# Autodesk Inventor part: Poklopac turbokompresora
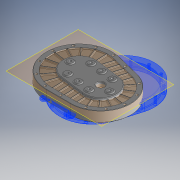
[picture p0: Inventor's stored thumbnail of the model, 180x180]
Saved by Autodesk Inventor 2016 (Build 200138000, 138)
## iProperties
Created: 2015-08
Part Number: Poklopac turbokompresora
Material: Generic
Document SubType Name: Modeling
Designer: stank
Density: 1 g/cm^3
Appearance: Default
Mass: 768.243 g
Surface Area: 1861.56 cm^2
Volume: 768.243 cm^3
Author: stank
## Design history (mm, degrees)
workplane "Work Plane3"
sketch "Sketch3"
  geometry: L1 (25.713, -105.228)-(-56.137, -104.923); L2 (26.085, -5.229)-(-52.114, 11.649); L3 (26.085, -5.229)-(-55.727, 5.076); L4 (25.769, -90.228)-(-56.081, -89.923); L5 (-32.512, 97.196)-(46.857, 77.194); L6 (50.522, 91.74)-(-28.846, 111.741); C1 r 9 at (26.085, -5.229) reference; C2 r 4.5 at (43.468, -93.366) reference; C3 r 4.5 at (-58.597, -126.199) reference; C4 r 4.5 at (-148.255, -75.856) reference; C5 r 4.5 at (-134.233, 101.873) reference; C6 r 4.5 at (-46.759, 125.523) reference; C7 r 4.5 at (25.538, 82.325) reference; A1 r 100 centre (26.085, -5.229) between (25.713, -105.228) and (50.522, 91.74); A2 r 110 centre (-55.727, 5.076) between (-28.846, 111.741) and (-56.137, -104.923); A3 r 85 centre (26.085, -5.229) between (25.769, -90.228) and (46.857, 77.194); A4 r 95 centre (-55.727, 5.076) between (-32.512, 97.196) and (-56.081, -89.923); 1 further point
  constraints: 12 end point, 8 point on circle, 6 tangent, 4 centre point, 2 parallel, 2 other
  dimensions: "d7" = 110 radius of A2; "d8" = 100 radius of A1; "d18" = 5 deg angle of L2 L3; "d26" = 15 distance between parallel lines of L1 L4; "d148" = 15 radial gap between concentric circles of A1 A3
extrude "Extrusion1" new body sketch "Sketch3" distance "d13" = 25; taper "d14" = 0 deg
sketch "Sketch7"
  geometry: L1 (50.522, 91.74)-(-28.846, 111.741) reference; L2 (-56.137, -104.923)-(25.713, -105.228) reference; C1 r 4 at (-41.402, 31.566) reference; C2 r 4 at (-38.197, -5.064) reference; C3 r 4 at (-13.762, -8.715) reference; C4 r 4 at (-4.556, 20.483) reference; C5 r 4 at (22.599, 34.619) reference; C6 r 4 at (51.797, 25.413) reference; C7 r 4 at (65.933, -1.742) reference; C8 r 4 at (56.727, -30.94) reference; C9 r 4 at (31.273, -44.891) reference; C10 r 4 at (0.374, -35.87) reference; A1 r 110 centre (-55.727, 5.076) between (-28.846, 111.741) and (-56.137, -104.923) reference; A2 r 100 centre (26.085, -5.229) between (25.713, -105.228) and (50.522, 91.74) reference; 1 further point
extrude "Extrusion3" join sketch "Sketch7" distance "d42" = 10; taper "d43" = 0 deg
sketch "Sketch8"
  geometry: L1 (25.769, -90.228)-(-56.081, -89.923) reference; L2 (-32.512, 97.196)-(46.857, 77.194) reference; C1 r 4 at (65.933, -1.742) reference; C2 r 4 at (56.727, -30.94) reference; C3 r 4 at (31.273, -44.891) reference; C4 r 4 at (0.374, -35.87) reference; C5 r 4 at (-13.762, -8.715) reference; C6 r 4 at (-38.197, -5.064) reference; C7 r 4 at (-4.556, 20.483) reference; C8 r 4 at (22.599, 34.619) reference; C9 r 4 at (51.797, 25.413) reference; C10 r 4 at (-41.402, 31.566) reference; C11 r 10 at (65.933, -1.742); C12 r 10 at (56.727, -30.94); C13 r 4 at (31.273, -44.891) reference; C14 r 10 at (31.273, -44.891); C15 r 10 at (0.374, -35.87); C16 r 4 at (-13.762, -8.715) reference; C17 r 10 at (-13.762, -8.715); C18 r 10 at (-38.197, -5.064); C19 r 10 at (-41.402, 31.566); C20 r 10 at (-4.556, 20.483); C21 r 4 at (22.599, 34.619) reference; C22 r 10 at (22.599, 34.619); C23 r 10 at (51.797, 25.413); A1 r 85 centre (26.085, -5.229) between (25.769, -90.228) and (46.857, 77.194) reference; A2 r 95 centre (-55.727, 5.076) between (-32.512, 97.196) and (-56.081, -89.923) reference; 1 further point
  constraints: 10 centre point, 10 coincident
  dimensions: "d44" = 20 diameter of C11; "d45" = 20 diameter of C12; "d46" = 20 diameter of C14; "d47" = 20 diameter of C15; "d48" = 20 diameter of C17; "d49" = 20 diameter of C20; "d50" = 20 diameter of C22; "d51" = 20 diameter of C23; "d52" = 20 diameter of C18; "d54" = 20 diameter of C19
extrude "Extrusion5" cut sketch "Sketch8" distance "d58" = 5; taper "d59" = 0 deg
sketch "Sketch10"
  geometry: C1 r 10 at (26.085, -5.229) reference; C2 r 11 at (26.085, -5.229); C3 r 16 at (26.085, -5.229); 1 further point
  constraints: 2 centre point, 2 coincident
  dimensions: "d60" = 1 radial gap between concentric circles of C1 C2; "d61" = 5 radial gap between concentric circles of C2 C3
extrude "Extrusion6" join sketch "Sketch10" distance "d62" = 3; taper "d63" = 0 deg
sketch "Sketch11"
  geometry: C1 r 11 at (0, 0) reference; 1 further point
extrude "Extrusion7" cut sketch "Sketch11" stored distance "d64" = 17; taper "d65" = 0 deg
chamfer "Chamfer3" distance "d71" = 1; stored, may be unused: second distance "d72" = 2, angle "d73" = 45 deg
workplane "Work Plane4"
sketch "Sketch12"
  geometry: L1 (26.085, -5.229)-(142.594, 145.734); L2 (26.085, -5.229)-(154.434, 22.85); L3 (26.085, -5.229)-(167.155, -24.202); L4 (26.085, -5.229)-(157.504, 77.979); L5 (101.371, 11.241)-(82.975, 7.217); L6 (89.461, -13.752)-(105.105, -15.856); L7 (75.965, 59.402)-(67.391, 48.291); L8 (92.041, 36.531)-(78.659, 28.059); L9 (-29.09, 110.772)-(50.278, 90.77) reference; L10 (25.717, -104.228)-(-56.133, -103.923) reference; L11 (-25.39, 100.364)-(51.872, 75.766) reference; L12 (30.981, -90.088)-(-49.967, -94.758) reference; L13 (-55.727, 5.076)-(-59.81, 104.993); L14 (-55.727, 5.076)-(-93.737, 97.571); L15 (-55.727, 5.076)-(-123.08, 78.992); L16 (-55.727, 5.076)-(-144.299, 51.499); L17 (-55.727, 5.076)-(-154.834, 18.406); L18 (-55.727, 5.076)-(-153.416, -16.295); L19 (-55.727, 5.076)-(26.085, -5.229); L20 (26.085, -5.229)-(51.872, 75.766); L21 (26.085, -5.229)-(51.872, 75.766); L22 (4.813, -2.549)-(31.782, 82.161); L23 (4.813, -2.549)-(8.443, -91.388); L24 (12.725, 88.229)-(-15.367, -0.007); L25 (-15.367, -0.007)-(-11.586, -92.543); L26 (-31.615, -93.699)-(-35.547, 2.534); L27 (-55.727, 5.076)-(-25.39, 100.364); L28 (-6.333, 94.296)-(-35.547, 2.534); L29 (49.768, 69.156)-(45.412, 55.475); L30 (49.768, 69.156)-(44.535, 52.72); L31 (29.678, 75.552)-(25.322, 61.871); L32 (9.933, 79.461)-(6.511, 68.711); L33 (-8.264, 88.229)-(-12.767, 74.086); L34 (-28.182, 91.595)-(-33.756, 74.086); L35 (-59.441, 95.979)-(-58.836, 81.156); L36 (-90.32, 89.255)-(-83.292, 72.154); L37 (-119.318, 74.864)-(-107.974, 62.414); L38 (-121.726, 39.668)-(-133.857, 46.026); L39 (-122.61, 14.072)-(-138.942, 16.268); L40 (-117.386, -8.413)-(-135.718, -12.423); L41 (-52.925, -63.49)-(-52.216, -80.841); L42 (-32.666, -67.96)-(-32.069, -82.577); L43 (-12.596, -67.814)-(-11.825, -86.696); L44 (7.37, -65.125)-(8.077, -82.428); L45 (26.085, -5.229)-(101.371, -44.688); L46 (26.085, -5.229)-(83.335, -68.057); L47 (26.085, -5.229)-(58.394, -83.849); L48 (26.085, -5.229)-(29.556, -90.158); L49 (-55.727, 5.076)-(-140.216, -48.418); L50 (-55.727, 5.076)-(-116.824, -74.089); L51 (-55.727, 5.076)-(-86.064, -90.211); L52 (-55.727, 5.076)-(-51.644, -94.84); L53 (83.335, -35.235)-(95.897, -41.818); L54 (65.44, -48.418)-(77.011, -61.116); L55 (49.052, -61.116)-(54.383, -74.089); L56 (28.634, -67.603)-(29.2, -81.44); L57 (-78.06, -65.073)-(-82.518, -79.075); L58 (-97.971, -49.661)-(-106.812, -61.116); L59 (-110.873, -29.84)-(-129.792, -41.818); C1 r 11 at (26.085, -5.229); C2 r 11 at (26.085, -5.229) reference; A1 r 100 centre (26.085, -5.229) between (25.713, -105.228) and (50.522, 91.74) reference; A2 r 110 centre (-55.727, 5.076) between (-28.846, 111.741) and (-56.137, -104.923) reference; A3 r 99 centre (26.085, -5.229) between (25.717, -104.228) and (50.278, 90.77) reference; A4 r 109 centre (-55.727, 5.076) between (-29.09, 110.772) and (-56.133, -103.923) reference; A5 r 85 centre (26.085, -5.229) between (30.981, -90.088) and (51.872, 75.766) reference; A6 r 100 centre (-55.727, 5.076) between (-25.39, 100.364) and (-49.967, -94.758) reference; A7 r 85 centre (26.085, -5.229) between (25.769, -90.228) and (46.857, 77.194) reference; A8 r 85 centre (26.085, -5.229) between (25.769, -90.228) and (46.857, 77.194) reference; 3 further points; 3 other entities
  constraints: 110 end point, 54 point on line, 14 point on circle, 6 parallel, 1 centre point, 1 coincident, 1 collinear, 1 perpendicular, 25 other
  dimensions: "d81" = 20 deg angle of L1 L4; "d82" = 20 deg angle of L2 L4; "d83" = 20 deg angle of L2 L3; "d194" = 20 deg angle of L13 L27; "d195" = 20 deg angle of L14 L13; "d196" = 20 deg angle of L14 L15; "d199" = 20 deg angle of L17 L16; "d200" = 20 deg angle of L17 L18; "d206" = 20 deg angle of L20 L1; "d207" = 20 deg angle of L15 L16; "d208" = 20 deg angle of L45 L3; "d209" = 20 deg angle of L46 L45; "d211" = 20 deg angle of L47 L46; "d212" = 20 deg angle of L48 L47; "d213" = 20 deg angle of L49 L18; "d214" = 20 deg angle of L50 L49; "d215" = 20 deg angle of L51 L50; "d216" = 20 deg angle of L51 L52; "d217" = 20 distance between parallel lines of L27 L28; "d218" = 20 distance between parallel lines of L24 L28; "d219" = 20 distance between parallel lines of L24 L22
  node "Projected Loop13"
sketch "Sketch13"
  geometry: L1 (26.085, -5.229)-(-31.513, 2.026); L2 (26.085, -5.229)-(-174.711, 20.063) reference; L3 (-55.727, 5.076)-(26.085, -5.229); L4 (-62.6, -49.493)-(19.212, -59.798); L5 (32.959, 49.34)-(-48.853, 59.645); A1 r 100 centre (-55.727, 5.076) between (-25.39, 100.364) and (-49.967, -94.758) reference; A2 r 55 centre (-55.727, 5.076) between (-48.853, 59.645) and (-62.6, -49.493); A3 r 55 centre (26.085, -5.229) between (19.212, -59.798) and (32.959, 49.34); 3 further points
  constraints: 12 end point, 4 point on circle, 4 tangent, 2 centre point, 2 collinear, 2 midpoint, 1 parallel
  dimensions: "d220" = 55 radius of A3
extrude "Extrusion8" join sketch "Sketch13" distance "d87" = 10; taper "d88" = 0 deg
fillet "Fillet9" dims "d99" = 1
fillet "Fillet10" dims "d100" = 2
chamfer "Chamfer4" distance "d138" = 1; stored, may be unused: second distance "d139" = 2, angle "d140" = 45 deg
fillet "Fillet12" dims "d150" = 2
sketch "Sketch18"
  geometry: C1 r 4 at (137.394, 67.018) reference; C2 r 4 at (95.482, 99.553) reference; C3 r 4 at (42.917, 106.773) reference; C4 r 4 at (-9.005, 94.468) reference; C5 r 4 at (-82.286, 68.869) reference; C6 r 4 at (-111.806, 30.842) reference; C7 r 4 at (-118.356, -16.851) reference; C8 r 4 at (-100.183, -61.429) reference; C9 r 4 at (-62.156, -90.949) reference; C10 r 4 at (15.184, -97.576) reference; C11 r 4 at (68.536, -96.62) reference; C12 r 4 at (150.203, -34.679) reference; C13 r 4 at (117.668, -76.591) reference; C14 r 4 at (157.423, 17.886) reference; C15 r 4 at (137.394, 67.018) reference; C16 r 4 at (95.482, 99.553) reference; C17 r 4 at (42.917, 106.773) reference; C18 r 4 at (-9.005, 94.468) reference; C19 r 4 at (-81.984, 68.471) reference; C20 r 4 at (-111.345, 30.648) reference; C21 r 4 at (-117.86, -16.788) reference; C22 r 4 at (-99.785, -61.127) reference
hole "Hole1" sketch "Sketch18" at (15.184, -97.576), (-62.156, -90.949), (-100.183, -61.429), (-118.356, -16.851), (-111.345, 30.648), (-81.984, 68.471), (-9.005, 94.468), (42.917, 106.773), (95.482, 99.553), (137.394, 67.018), (157.423, 17.886), (150.203, -34.679)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 diameter "d155" = 8; stored, may be unused: countersink angle "d159" = 90 deg, drill point angle "d161" = 118 deg; dims "d156" = 6, "d157" = 4, "d158" = 2, "d160" = 8
chamfer "Chamfer6" distance "d162" = 2; stored, may be unused: second distance "d163" = 2, angle "d164" = 45 deg
sketch "Sketch19"
  geometry: C1 r 11 at (26.085, -5.229) reference; C2 r 12 at (26.085, -5.229); 1 further point
  constraints: 1 centre point, 1 coincident
  dimensions: "d166" = 1 radial gap between concentric circles of C2 C1
extrude "Extrusion11" cut sketch "Sketch19" stored distance "d167" = 10; taper "d168" = 0 deg
workplane "Work Plane7"
sketch "Sketch21"
  geometry: L1 (-60, -27.257)-(-60, 50.054) reference; L2 (-60, 13.886)-(-59, 13.886); L3 (-59, 13.886)-(-59, 14.886); L4 (-59, 14.886)-(-60, 14.886); L5 (-60, 14.886)-(-60, 13.886); L6 (-47, 23.386)-(-60, 23.386); L7 (-60, 23.386)-(-60, 27.386); L8 (-60, 27.386)-(-47, 27.386); L9 (-47, 27.386)-(-47, 23.386); L10 (-50.113, -0.114)-(-87.752, -0.114) reference; 1 further point
  constraints: 18 end point, 4 horizontal, 4 parallel, 2 perpendicular, 2 point on line
  dimensions: "d176" = 28 diameter of L2 L10; "d177" = 1 distance of L2.start L2.end; "d178" = 1 distance of L2.end L3.end; "d179" = 4 distance between parallel lines of L8 L6; "d180" = 47 diameter of L6 L10; "d181" = 13 distance of L6.start L6.end
revolve "Revolution1" sketch "Sketch21" stored, may be unused: angle "d182" = 90 deg
workplane "Work Plane8"
sketch "Sketch22"
  geometry: L1 (1, 15)-(0, 15); L2 (0, 15)-(0, 16); L3 (0, 16)-(1, 16); L4 (1, 16)-(1, 15); L5 (1, 23.5)-(-12, 23.5); L6 (-12, 23.5)-(-12, 26.5); L7 (-12, 26.5)-(1, 26.5); L8 (1, 26.5)-(1, 23.5); L9 (-0.6, 23.5)-(-11.4, 23.5) reference; L10 (0, 0)-(17.307, 0); 4 further points; 2 other entities
  constraints: 20 end point, 4 horizontal, 4 parallel, 2 perpendicular, 1 point on line, 5 other
  dimensions: "d183" = 1 distance of L3.end L1.start; "d184" = 1 distance of L1.start L1.end; "d185" = 30 diameter of L1 L10; "d186" = 47 diameter of L5 L10; "d187" = 13 distance between parallel lines of L8 L6; "d188" = 3 distance of L7.end L5.start
revolve "Revolution2" sketch "Sketch22" stored, may be unused: angle "d189" = 90 deg
feature "Rib7" dims "d227" = 5, "d228" = 1, "d229" = 0, "d230" = 0, "d231" = 1, "d232" = 1
feature "Rib8" dims "d233" = 5, "d234" = 1, "d235" = 0, "d236" = 0, "d237" = 1, "d238" = 1
feature "Rib9" dims "d239" = 5, "d240" = 1, "d241" = 0, "d242" = 0, "d243" = 1, "d244" = 1
feature "Rib10" dims "d245" = 5, "d246" = 1, "d247" = 0, "d248" = 0, "d249" = 1, "d250" = 1
fillet "Fillet15" dims "d251" = 2
fillet "Fillet16" dims "d252" = 0.5
sketch "Sketch23"
  geometry: L1 (19.462, -57.813)-(-62.35, -47.508) reference; L2 (-49.103, 57.661)-(32.709, 47.356) reference; L3 (26.085, -5.229)-(-55.727, 5.076); L4 (26.085, -5.229)-(-55.727, 5.076); L5 (30.459, 29.497)-(-51.353, 39.802); L6 (-60.101, -29.649)-(21.712, -39.954); C1 r 12 at (26.085, -5.229) reference; A1 r 53 centre (-55.727, 5.076) between (-49.103, 57.661) and (-62.35, -47.508) reference; A2 r 53 centre (26.085, -5.229) between (19.462, -57.813) and (32.709, 47.356) reference; A3 r 35 centre (26.085, -5.229) between (21.712, -39.954) and (30.459, 29.497); A4 r 35 centre (-55.727, 5.076) between (-51.353, 39.802) and (-60.101, -29.649); 10 further points
  constraints: 10 end point, 6 point on circle, 4 coincident, 4 tangent, 3 midpoint, 2 centre point, 2 equal length
  dimensions: "d253" = 35 radius of A3
hole "Hole3" sketch "Sketch23" at (60.811, -9.603), (-90.452, 9.45), (30.459, 29.497), (21.712, -39.954), (-60.101, -29.649), (-51.353, 39.802), (-10.447, 34.649), (-19.195, -34.802) diameter "d254" = 8; stored, may be unused: countersink angle "d258" = 90 deg, drill point angle "d260" = 118 deg; dims "d255" = 6, "d256" = 4, "d257" = 2, "d259" = 10
sketch "Sketch24"
  geometry: C1 r 4 at (-51.353, 39.802) reference; C2 r 4 at (-10.447, 34.649) reference; C3 r 4 at (30.459, 29.497) reference; C4 r 4 at (60.811, -9.603) reference; C5 r 4 at (21.712, -39.954) reference; C6 r 4 at (-19.195, -34.802) reference; C7 r 4 at (-60.101, -29.649) reference; C8 r 4 at (-90.452, 9.45) reference; C9 r 10 at (-51.353, 39.802); C10 r 10 at (-10.447, 34.649); C11 r 10 at (30.459, 29.497); C12 r 10 at (60.811, -9.603); C13 r 10 at (21.712, -39.954); C14 r 10 at (-19.195, -34.802); C15 r 10 at (-60.101, -29.649); C16 r 10 at (-90.452, 9.45); 1 further point
  constraints: 8 centre point, 8 coincident
  dimensions: "d261" = 20 diameter of C9; "d262" = 20 diameter of C10; "d263" = 20 diameter of C11; "d264" = 20 diameter of C12; "d265" = 20 diameter of C13; "d266" = 20 diameter of C14; "d267" = 20 diameter of C15; "d268" = 20 diameter of C16
extrude "Extrusion12" join sketch "Sketch24" distance "d269" = 3; taper "d270" = 0 deg
fillet "Fillet17" dims "d271" = 3
chamfer "Chamfer8" distance "d272" = 2; stored, may be unused: second distance "d273" = 2, angle "d274" = 45 deg
sketch "Sketch25"
  geometry: C1 r 4 at (-51.797, 25.413) reference; C2 r 4 at (-65.933, -1.742) reference; C3 r 4 at (-22.599, 34.619) reference; C4 r 4 at (4.556, 20.483) reference; C5 r 4 at (13.762, -8.715) reference; C6 r 4 at (-0.374, -35.87) reference; C7 r 4 at (-31.273, -44.891) reference; C8 r 4 at (-56.727, -30.94) reference; A1 r 4 centre (41.402, 31.566) between (37.652, 30.172) and (44.631, 33.926) reference; A2 r 4 centre (41.402, 31.566) between (40.48, 35.458) and (38.662, 34.481) reference; A3 r 4 centre (41.402, 31.566) between (38.662, 34.481) and (37.652, 30.172) reference; A4 r 4 centre (41.402, 31.566) between (44.631, 33.926) and (40.48, 35.458) reference; A5 r 4 centre (38.197, -5.064) between (40.13, -8.566) and (34.403, -3.797) reference; A6 r 4 centre (38.197, -5.064) between (34.403, -3.797) and (40.13, -8.566) reference; 1 further point
extrude "Extrusion13" join sketch "Sketch25" stored distance "d275" = 2.5; taper "d276" = 0 deg
fillet "Fillet18" dims "d277" = 2
chamfer "Chamfer9" distance "d278" = 1; stored, may be unused: second distance "d279" = 2, angle "d280" = 45 deg
body "Solid1"
node "Reference1"
node "Reference2"
node "Reference12"
node "Reference13"
node "Reference14"
node "Reference15"
node "Reference16"
node "Reference17"
node "Reference25"
node "Reference26"
node "Reference27"
node "Reference28"
node "Reference29"
node "Reference30"
node "Reference31"
node "Reference32"
node "Reference33"
node "Reference34"
node "Reference35"
node "Reference57"
node "Projected Loop14"
node "Reference58"
node "Reference59"
node "Reference60"
node "Reference61"
node "Reference62"
node "Reference63"
node "Reference64"
node "Reference65"
node "Reference66"
node "Reference67"
node "Reference68"
node "Reference69"
node "Reference70"
node "Reference71"
node "Reference72"
node "Reference73"
node "Reference74"
node "Reference75"
node "Reference76"
node "Reference77"
node "Reference78"
node "Reference79"
other parameters: "d89" = 4
